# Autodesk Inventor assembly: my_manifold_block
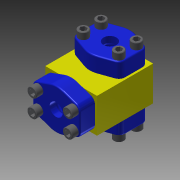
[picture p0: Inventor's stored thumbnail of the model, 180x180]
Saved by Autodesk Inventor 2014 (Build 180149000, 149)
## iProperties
Created: 2009-01
Part Number: my_manifold_block
Document SubType Name: Assembly
Designer: pekj
RuleStatus: InUse
Author: pekj
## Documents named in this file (6)
- C:\Users\iTools\Desktop\tutorial files\iLogic\my_manifold_block.iam
- C:\Users\iTools\Desktop\tutorial files\iLogic\manifold_block.ipt
- D:\iLogic-Main\Tutorials\3) Manifold Assembly\union_cap.ipt
- D:\iLogic-Main\Tutorials\3) Manifold Assembly\Screw.ipt
- C:\Users\iTools\Desktop\tutorial files\iLogic\union_cap\union_cap [Model Code=100].ipt
- C:\Users\iTools\Desktop\tutorial files\iLogic\SHCS\Screw-02.ipt
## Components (16 placed, 8 different names)
1. manifold_block:1 — port_a_cap_center, port_a_cap_hole, port_a_cap_face, port_c_cap_center, port_c_cap_hole, port_c_cap_face, port_b_cap_center, port_b_cap_hole, port_b_cap_face
2. port_a_union — port_a_cap_face, port_a_cap_screw, port_a_cap_center, port_a_cap_hole
3. port_b_union — port_b_cap_center, port_b_cap_face, port_b_cap_screw, port_b_cap_hole
4. port_c_union — port_c_cap_center, port_c_cap_face, port_c_cap_screw, port_c_cap_hole
5. port_a_union_screw — port_a_cap_screw
6. Screw-02:4
7. Screw-02:5
8. Screw-02:6
9. port_b_union_screw — port_c_cap_screw
10. Screw-02:7
11. Screw-02:8
12. Screw-02:9
13. port_c_union_screw — port_b_cap_screw
14. Screw-02:10
15. Screw-02:11
16. Screw-02:12
## Component patterns: port_a_screw_pattern (4 elements), port_c_screw_pattern (4 elements), port_b_screw_pattern (4 elements)
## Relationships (12: Mate 9, Insert 3)
- port_a_cap_center [Mate]: manifold_block:1 ↔ port_a_union
- port_a_cap_hole [Mate]: manifold_block:1 ↔ port_a_union
- port_a_cap_face [Mate]: manifold_block:1 ↔ port_a_union
- port_a_cap_screw [Insert]: port_a_union ↔ port_a_union_screw
- port_c_cap_center [Mate]: manifold_block:1 ↔ port_c_union
- port_c_cap_hole [Mate]: manifold_block:1 ↔ port_c_union
- port_c_cap_face [Mate]: manifold_block:1 ↔ port_c_union
- port_c_cap_screw [Insert]: port_c_union ↔ port_b_union_screw
- port_b_cap_center [Mate]: manifold_block:1 ↔ port_b_union
- port_b_cap_hole [Mate]: manifold_block:1 ↔ port_b_union
- port_b_cap_face [Mate]: manifold_block:1 ↔ port_b_union
- port_b_cap_screw [Insert]: port_b_union ↔ port_c_union_screw
## Named parameters: port_a_y_dist_between_screws = 26.162 mm, port_a_x_dist_between_screws = 52.324 mm, port_c_y_dist_between_screws = 26.162 mm, port_c_x_dist_between_screws = 52.324 mm, port_b_y_dist_between_screws = 26.162 mm, port_b_x_dist_between_screws = 52.324 mm
